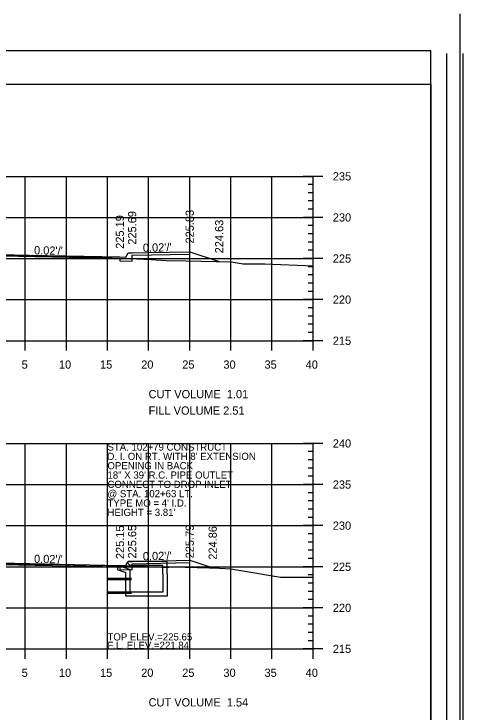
# Model space of a CAD drawing. Extents: x 1367903 to 1373764, y 376865 to 382130.
# Drawn here: x 1370324.4 to 1370433.6, y 377450.5 to 377620.4 of the extents above; entities that cross this region are included whole.
import ezdxf

# ---------------------------------------------------------------- set-up
doc = ezdxf.new("R2010")
doc.units = 0
for name, color, linetype in [('R_Axis', 7, 'Continuous'), ('R_Axis Annot', 7, 'Continuous'), ('R_Border', 7, 'Continuous'), ('R_Border PE', 7, 'Continuous'), ('R_Draft', 7, 'Continuous'), ('R_Exist Surface', 7, 'Continuous'), ('R_Fin Surface', 7, 'Continuous'), ('R_Fin Surface Annot', 7, 'Continuous'), ('R_Grid', 7, 'Continuous'), ('R_Water', 7, 'Continuous'), ('R_Water Annot', 7, 'Continuous')]:
    doc.layers.add(name, color=color, linetype=linetype)

msp = doc.modelspace()

# ---------------------------------------------------------------- linework, layer by layer
for p, q in [((1370349.6, 377486.18), (1370352.6, 377485.14)), ((1370351.94, 377486.81), (1370352.1, 377487.14)), ((1370351.94, 377486.81), (1370352.6, 377486.14)), ((1370361.6, 377487.14), (1370352.1, 377487.14)), ((1370360.6, 377486.14), (1370352.6, 377486.14)), ((1370360.6, 377484.14), (1370360.6, 377486.14)), ((1370361.6, 377484.14), (1370361.6, 377487.14)), ((1370349.6, 377485.12), (1370351.6, 377484.42)), ((1370351.6, 377484.14), (1370351.6, 377484.42)), ((1370352.6, 377484.14), (1370352.6, 377485.14))]:
    msp.add_line(p, q)
for points in [[(1370281.1, 377562.21), (1370281.1, 377561.54), (1370281.1, 377561.54), (1370281.1, 377560.18), (1370284.1, 377560.24), (1370284.1, 377560.91), (1370317.1, 377561.57), (1370350.1, 377560.91), (1370350.1, 377560.24), (1370353.1, 377560.18), (1370353.1, 377561.62), (1370367.1, 377561.9), (1370367.1, 377562.49)], [(1370281.1, 377487.14), (1370281.1, 377486.47), (1370281.1, 377486.47), (1370281.1, 377485.11), (1370284.1, 377485.17), (1370284.1, 377485.83), (1370317.1, 377486.49), (1370350.1, 377485.83), (1370350.1, 377485.17), (1370353.1, 377485.11), (1370353.1, 377486.55), (1370367.1, 377486.83), (1370367.1, 377487.42)], [(1370349.6, 377485.12), (1370349.6, 377486.18)]]:
    msp.add_lwpolyline(points)
at = {"layer": 'R_Axis'}
for p, q in [((1370399.5, 377580.84), (1370394.7, 377580.84)), ((1370397.1, 377540.84), (1370397.1, 377580.84)), ((1370397.1, 377578.84), (1370395.9, 377578.84)), ((1370397.1, 377576.84), (1370395.9, 377576.84)), ((1370397.1, 377574.84), (1370395.9, 377574.84)), ((1370397.1, 377572.84), (1370395.9, 377572.84)), ((1370399.5, 377570.84), (1370394.7, 377570.84)), ((1370397.1, 377568.84), (1370395.9, 377568.84)), ((1370397.1, 377566.84), (1370395.9, 377566.84)), ((1370397.1, 377564.84), (1370395.9, 377564.84)), ((1370397.1, 377562.84), (1370395.9, 377562.84)), ((1370399.5, 377560.84), (1370394.7, 377560.84)), ((1370397.1, 377558.84), (1370395.9, 377558.84)), ((1370397.1, 377556.84), (1370395.9, 377556.84)), ((1370397.1, 377554.84), (1370395.9, 377554.84)), ((1370397.1, 377552.84), (1370395.9, 377552.84)), ((1370399.5, 377550.84), (1370394.7, 377550.84)), ((1370397.1, 377548.84), (1370395.9, 377548.84)), ((1370397.1, 377546.84), (1370395.9, 377546.84)), ((1370397.1, 377544.84), (1370395.9, 377544.84)), ((1370327.1, 377538.44), (1370327.1, 377543.24)), ((1370337.1, 377538.44), (1370337.1, 377543.24)), ((1370347.1, 377538.44), (1370347.1, 377543.24)), ((1370357.1, 377538.44), (1370357.1, 377543.24)), ((1370367.1, 377538.44), (1370367.1, 377543.24)), ((1370377.1, 377538.44), (1370377.1, 377543.24)), ((1370387.1, 377538.44), (1370387.1, 377543.24)), ((1370397.1, 377542.84), (1370395.9, 377542.84)), ((1370397.1, 377538.44), (1370397.1, 377543.24)), ((1370237.1, 377540.84), (1370397.1, 377540.84)), ((1370399.5, 377540.84), (1370394.7, 377540.84)), ((1370399.5, 377515.84), (1370394.7, 377515.84)), ((1370397.1, 377465.84), (1370397.1, 377515.84)), ((1370397.1, 377513.84), (1370395.9, 377513.84)), ((1370397.1, 377511.84), (1370395.9, 377511.84)), ((1370397.1, 377509.84), (1370395.9, 377509.84)), ((1370397.1, 377507.84), (1370395.9, 377507.84)), ((1370399.5, 377505.84), (1370394.7, 377505.84)), ((1370397.1, 377503.84), (1370395.9, 377503.84)), ((1370397.1, 377501.84), (1370395.9, 377501.84)), ((1370397.1, 377499.84), (1370395.9, 377499.84)), ((1370397.1, 377497.84), (1370395.9, 377497.84)), ((1370399.5, 377495.84), (1370394.7, 377495.84)), ((1370397.1, 377493.84), (1370395.9, 377493.84)), ((1370397.1, 377491.84), (1370395.9, 377491.84)), ((1370397.1, 377489.84), (1370395.9, 377489.84)), ((1370397.1, 377487.84), (1370395.9, 377487.84)), ((1370399.5, 377485.84), (1370394.7, 377485.84)), ((1370397.1, 377483.84), (1370395.9, 377483.84)), ((1370397.1, 377481.84), (1370395.9, 377481.84)), ((1370397.1, 377479.84), (1370395.9, 377479.84)), ((1370397.1, 377477.84), (1370395.9, 377477.84)), ((1370399.5, 377475.84), (1370394.7, 377475.84)), ((1370397.1, 377473.84), (1370395.9, 377473.84)), ((1370397.1, 377471.84), (1370395.9, 377471.84)), ((1370397.1, 377469.84), (1370395.9, 377469.84)), ((1370327.1, 377463.44), (1370327.1, 377468.24)), ((1370337.1, 377463.44), (1370337.1, 377468.24)), ((1370347.1, 377463.44), (1370347.1, 377468.24)), ((1370357.1, 377463.44), (1370357.1, 377468.24)), ((1370367.1, 377463.44), (1370367.1, 377468.24)), ((1370377.1, 377463.44), (1370377.1, 377468.24)), ((1370387.1, 377463.44), (1370387.1, 377468.24)), ((1370397.1, 377467.84), (1370395.9, 377467.84)), ((1370397.1, 377463.44), (1370397.1, 377468.24)), ((1370237.1, 377465.84), (1370397.1, 377465.84)), ((1370399.5, 377465.84), (1370394.7, 377465.84))]:
    msp.add_line(p, q, dxfattribs=at)
at = {"layer": 'R_Border'}
for p, q in [((1370432.77, 377620.35), (1370432.77, 377279.12)), ((1370221.41, 377611.47), (1370425.73, 377611.47)), ((1370425.73, 377280.59), (1370425.73, 377611.47))]:
    msp.add_line(p, q, dxfattribs=at)
at = {"layer": 'R_Border PE'}
for p, q in [((1370429.65, 377288.8), (1370429.65, 377610.76)), ((1370433.57, 377288.8), (1370433.57, 377610.76)), ((1370221.41, 377603.25), (1370425.73, 377603.25)), ((1370425.73, 377603.25), (1370425.73, 377288.8))]:
    msp.add_line(p, q, dxfattribs=at)
at = {"layer": 'R_Exist Surface'}
for points in [[(1370321.08, 377561.61), (1370324.71, 377561.57), (1370327.95, 377561.49), (1370347.5, 377561.05), (1370349.07, 377560.95), (1370352.64, 377560.81), (1370357.61, 377560.63), (1370361.39, 377560.35), (1370362.07, 377560.31), (1370362.92, 377560.33), (1370366.23, 377560.25), (1370377.2, 377560.05), (1370380.07, 377559.57), (1370385.38, 377559.53), (1370397.1, 377559.08)], [(1370321.12, 377486.53), (1370337.44, 377486.35), (1370338.87, 377486.33), (1370346.76, 377486.15), (1370352.51, 377486.02), (1370359.43, 377485.78), (1370360.24, 377485.73), (1370361.99, 377485.77), (1370362.99, 377485.8), (1370371.93, 377485.57), (1370374.34, 377485.51), (1370377.17, 377485.32), (1370378.01, 377485.19), (1370379.57, 377484.91), (1370389.19, 377483.32), (1370397.1, 377483.26)]]:
    msp.add_lwpolyline(points, dxfattribs=at)
at = {"layer": 'R_Fin Surface'}
for points in [[(1370278.8, 377561.44), (1370281.1, 377562.21), (1370282.1, 377562.21), (1370282.6, 377561.21), (1370284.1, 377561.24), (1370306.1, 377561.68), (1370317.1, 377561.9), (1370328.1, 377561.68), (1370350.1, 377561.24), (1370351.6, 377561.21), (1370352.1, 377562.21), (1370353.1, 377562.21), (1370357.1, 377562.29), (1370367.1, 377562.49), (1370374.27, 377560.1)], [(1370278.21, 377486.17), (1370281.1, 377487.14), (1370282.1, 377487.14), (1370282.6, 377486.14), (1370284.1, 377486.17), (1370306.1, 377486.61), (1370317.1, 377486.83), (1370328.1, 377486.61), (1370350.1, 377486.17), (1370351.6, 377486.14), (1370352.1, 377487.14), (1370353.1, 377487.14), (1370357.1, 377487.22), (1370367.1, 377487.42), (1370372.69, 377485.56)]]:
    msp.add_lwpolyline(points, dxfattribs=at)
at = {"layer": 'R_Grid'}
for p, q in [((1370237.1, 377580.84), (1370397.1, 377580.84)), ((1370327.1, 377540.84), (1370327.1, 377580.84)), ((1370337.1, 377540.84), (1370337.1, 377580.84)), ((1370347.1, 377540.84), (1370347.1, 377580.84)), ((1370357.1, 377540.84), (1370357.1, 377580.84)), ((1370367.1, 377540.84), (1370367.1, 377580.84)), ((1370377.1, 377540.84), (1370377.1, 377580.84)), ((1370387.1, 377540.84), (1370387.1, 377580.84)), ((1370397.1, 377540.84), (1370397.1, 377580.84)), ((1370237.1, 377570.84), (1370397.1, 377570.84)), ((1370237.1, 377560.84), (1370397.1, 377560.84)), ((1370237.1, 377550.84), (1370397.1, 377550.84)), ((1370237.1, 377540.84), (1370397.1, 377540.84)), ((1370237.1, 377515.84), (1370397.1, 377515.84)), ((1370327.1, 377465.84), (1370327.1, 377515.84)), ((1370337.1, 377465.84), (1370337.1, 377515.84)), ((1370347.1, 377465.84), (1370347.1, 377515.84)), ((1370357.1, 377465.84), (1370357.1, 377515.84)), ((1370367.1, 377465.84), (1370367.1, 377515.84)), ((1370377.1, 377465.84), (1370377.1, 377515.84)), ((1370387.1, 377465.84), (1370387.1, 377515.84)), ((1370397.1, 377465.84), (1370397.1, 377515.84)), ((1370237.1, 377505.84), (1370397.1, 377505.84)), ((1370237.1, 377495.84), (1370397.1, 377495.84)), ((1370237.1, 377485.84), (1370397.1, 377485.84)), ((1370237.1, 377475.84), (1370397.1, 377475.84)), ((1370237.1, 377465.84), (1370397.1, 377465.84))]:
    msp.add_line(p, q, dxfattribs=at)
at = {"layer": 'R_Water'}
for p, q in [((1370352.92, 377483), (1370347.12, 377482.97)), ((1370352.92, 377482.67), (1370347.12, 377482.63)), ((1370352.92, 377479.67), (1370347.12, 377479.63)), ((1370352.92, 377479.34), (1370347.12, 377479.3))]:
    msp.add_line(p, q, dxfattribs=at)
for points in [[(1370361.6, 377484.14), (1370361.6, 377478.67), (1370356.6, 377478.67), (1370351.6, 377478.67), (1370351.6, 377484.14)], [(1370360.6, 377484.14), (1370360.6, 377479.67), (1370356.6, 377479.67), (1370352.6, 377479.67), (1370352.6, 377484.14)]]:
    msp.add_lwpolyline(points, dxfattribs=at)

# ---------------------------------------------------------------- texts
at = {"layer": 'R_Axis Annot'}
for s, p in [('235', (1370401.9, 377579.84)), ('230', (1370401.9, 377569.84)), ('225', (1370401.9, 377559.84)), ('220', (1370401.9, 377549.84)), ('215', (1370401.9, 377539.84)), ('5', (1370326.23, 377534.04)), ('10', (1370335.3, 377534.04)), ('15', (1370345.29, 377534.04)), ('20', (1370355.3, 377534.04)), ('25', (1370365.29, 377534.04)), ('30', (1370375.3, 377534.04)), ('35', (1370385.29, 377534.04)), ('40', (1370395.3, 377534.04)), ('CUT VOLUME  1.01', (1370357.1, 377526.84)), ('FILL VOLUME 2.51', (1370357.1, 377522.84)), ('240', (1370401.9, 377514.84)), ('235', (1370401.9, 377504.84)), ('230', (1370401.9, 377494.84)), ('225', (1370401.9, 377484.84)), ('220', (1370401.9, 377474.84)), ('215', (1370401.9, 377464.84)), ('5', (1370326.23, 377459.04)), ('10', (1370335.3, 377459.04)), ('15', (1370345.29, 377459.04)), ('20', (1370355.3, 377459.04)), ('25', (1370365.29, 377459.04)), ('30', (1370375.3, 377459.04)), ('35', (1370385.29, 377459.04)), ('40', (1370395.3, 377459.04)), ('CUT VOLUME  1.54', (1370357.1, 377451.84))]:
    msp.add_text(s, height=2, dxfattribs=at).set_placement(p)
at = {"layer": 'R_Draft'}
for s, p in [('STA. 102+79 CONSTRUCT', (1370347.1, 377514.09)), ("D. I. ON RT. WITH 8' EXTENSION", (1370347.1, 377511.82)), ('OPENING IN BACK', (1370347.1, 377509.55)), ('18" X 39\' R.C. PIPE OUTLET', (1370347.1, 377507.28)), ('CONNECT TO DROP INLET', (1370347.1, 377505.01)), ('@ STA. 102+63 LT.', (1370347.1, 377502.74)), ("TYPE MO = 4' I.D.", (1370347.1, 377500.47)), ("HEIGHT = 3.81'", (1370347.1, 377498.2))]:
    msp.add_text(s, height=1.75, dxfattribs=at).set_placement(p)
at = {"layer": 'R_Fin Surface Annot'}
for s, rotation, p in [('225.83', 90, (1370368.1, 377564.49)), ('225.19', 90, (1370351.11, 377563.21)), ('225.69', 90, (1370354.1, 377564.21)), ('224.63', 90, (1370375.27, 377562.1)), ("0.02'/'", 358.8542, (1370329.23, 377561.86)), ("0.02'/'", 1.1458, (1370355.73, 377562.46)), ('225.65', 90, (1370354.1, 377487.84)), ('225.79', 90, (1370368.1, 377487.88)), ('225.15', 90, (1370351.14, 377487.7)), ('224.86', 90, (1370373.69, 377487.56)), ("0.02'/'", 1.1458, (1370355.73, 377487.39)), ("0.02'/'", 358.8542, (1370329.23, 377486.78))]:
    msp.add_text(s, height=2, rotation=rotation, dxfattribs=at).set_placement(p)
at = {"layer": 'R_Water Annot'}
for s, p in [('TOP ELEV.=225.65', (1370347.1, 377467.89)), ('F.L. ELEV.=221.84', (1370347.1, 377465.84))]:
    msp.add_text(s, height=1.75, dxfattribs=at).set_placement(p)

doc.saveas('drawing.dxf')
